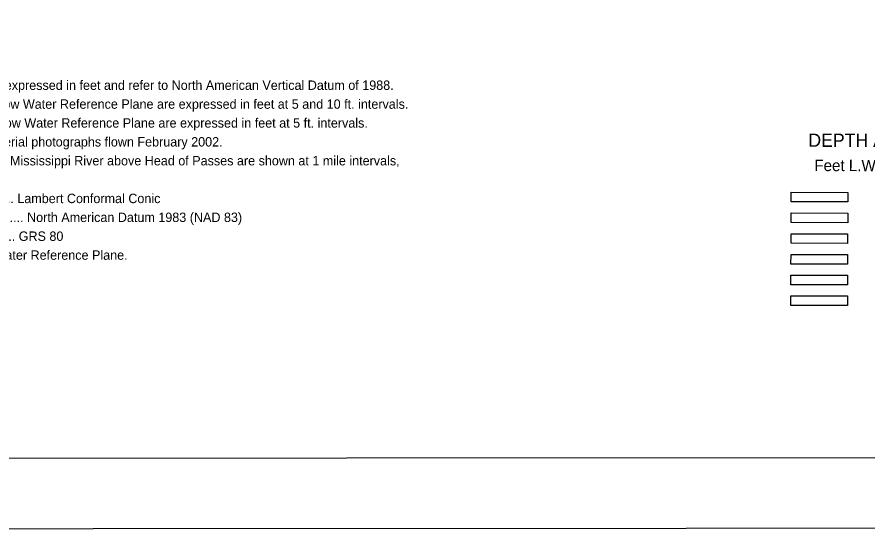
# Model space of a CAD drawing. Extents: x 3281947 to 3319794, y 715894 to 741249.
# Drawn here: x 3287110 to 3294621, y 716477 to 720999 of the extents above; entities that cross this region are included whole.
import ezdxf

# ---------------------------------------------------------------- set-up
doc = ezdxf.new("R2010")
doc.units = 0
for name, color, linetype in [('G-ANNO-NPLT', 7, 'Continuous'), ('V-ANNO-NOTE', 7, 'Continuous'), ('V-ANNO-SYMB', 7, 'Continuous'), ('V-TOPO-DPTH', 7, 'Continuous')]:
    doc.layers.add(name, color=color, linetype=linetype)

msp = doc.modelspace()

# ---------------------------------------------------------------- linework, layer by layer
at = {"layer": 'G-ANNO-NPLT'}
msp.add_lwpolyline([(3282544.2, 716477.2), (3319210.9, 716498.6), (3319196.8, 740665.2), (3282530.2, 740643.9)], close=True, dxfattribs=at)
at = {"layer": 'V-ANNO-SYMB'}
msp.add_lwpolyline([(3285294, 717103.9), (3318377.2, 717123.1), (3318363.9, 740039.7), (3285280.7, 740020.4), (3285294, 717103.9)], dxfattribs=at)
at = {"layer": 'V-TOPO-DPTH'}
for points in [[(3293950.5, 719451.2), (3294450.5, 719450), (3294450.3, 719365), (3293950.3, 719366.2)], [(3293950.5, 719451.2), (3294450.5, 719450), (3294450.3, 719365), (3293950.3, 719366.2)], [(3293950.1, 719268.2), (3294450.1, 719267), (3294449.8, 719182), (3293949.9, 719183.2)], [(3293950.1, 719268.2), (3294450.1, 719267), (3294449.8, 719182), (3293949.9, 719183.2)], [(3293949.6, 719085.2), (3294449.6, 719084), (3294449.4, 718999), (3293949.4, 719000.2)], [(3293949.6, 719085.2), (3294449.6, 719084), (3294449.4, 718999), (3293949.4, 719000.2)], [(3293949.2, 718902.2), (3294449.2, 718901), (3294448.9, 718816), (3293948.9, 718817.2)], [(3293949.2, 718902.2), (3294449.2, 718901), (3294448.9, 718816), (3293948.9, 718817.2)], [(3293948.7, 718719.2), (3294448.7, 718718), (3294448.5, 718633), (3293948.5, 718634.2)], [(3293948.7, 718719.2), (3294448.7, 718718), (3294448.5, 718633), (3293948.5, 718634.2)], [(3293948.3, 718536.2), (3294448.2, 718535), (3294448, 718450), (3293948, 718451.2)], [(3293948.3, 718536.2), (3294448.2, 718535), (3294448, 718450), (3293948, 718451.2)]]:
    msp.add_lwpolyline(points, close=True, dxfattribs=at)

# ---------------------------------------------------------------- texts
at = {"layer": 'V-ANNO-NOTE'}
for s, rotation, p in [('All elevations are expressed in feet and refer to North American Vertical Datum of 1988.', 0.00001, (3286126.1, 720355.1)), ('Contours below Low Water Reference Plane are expressed in feet at 5 and 10 ft. intervals.', 0.00001, (3286126.1, 720188.4)), ('Contours above Low Water Reference Plane are expressed in feet at 5 ft. intervals.', 0.00001, (3286126.1, 720021.7)), ('Planimetry from aerial photographs flown February 2002.', 0.00001, (3286126.1, 719855)), ('Distances on Mississippi River above Head of Passes are shown at 1 mile intervals,', 0.00001, (3286376.3, 719688.3)), ('Projection .............. Lambert Conformal Conic', 359.99998, (3286126.1, 719355)), ('Horizontal Datum ..... North American Datum 1983 (NAD 83)', 359.99998, (3286126.1, 719188.3)), ('Ellipsoid ................. GRS 80', 359.99998, (3286126.1, 719021.6)), ('L.W.R.P. - Low Water Reference Plane.', 359.99998, (3286126.1, 718854.9))]:
    msp.add_text(s, height=83, rotation=rotation, dxfattribs=at).set_placement(p)
at = {"layer": 'V-TOPO-DPTH'}
for s, height, rotation, p in [('DEPTH AREAS', 116.7, 359.85834, (3294102.2, 719852.5)), ('Feet L.W.R.P.', 100, 359.85833, (3294155.4, 719638.2))]:
    msp.add_text(s, height=height, rotation=rotation, dxfattribs=at).set_placement(p)

doc.saveas('drawing.dxf')
